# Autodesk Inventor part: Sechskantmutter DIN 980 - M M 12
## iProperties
Shininess: 64.0
Length Units: 11269
Angle Units: 11279
Time Units: 11290
Mass Units: 11283
Length Display Precision: 3
Angle Display Precision: 2
Compacted: True
Part Number: Sechskantmutter DIN 980 - M M 12
Document SubType Name: Standard Catalog Part
Created: 2004-12
Material: Standard
Description: Sechskantmutter, mit Klemmteil, Ganzmetallmutter
Vendor: NORM8
Designer: L.Vaida
Manufacturer: Standard
Standards Organization: Custom
Density: 0.0
Volumn: 0.0
Area: 0.0
PropertySet Name: Model Information
Control State: 0
Master: False
Checked Out: False
CNS_NB: Sechskantmutter DIN 980 - M M 12
CNS_NN: DIN 980
CNS_NT: Sechskantmutter, mit Klemmteil, Ganzmetallmutter
CNS_NBSYN: Sechskantmutter DIN 980 - M $NENN.
CNS_LINA: Sechskantmutter DIN 980 - M M 12
CNS_NENN: M 12
CNS_D: 12.000
CNS_D1: 10.106
CNS_P: 1.750
CNS_M: 12.000
CNS_S: 19.000
CNS_KT: X
PSOL_IDENT_0: {E:\CAD-Programme\cadenas\partsolutions\data\23d-libs\norm\din_en_iso\muttern\muttern_mit_klemmteil\
PSOL_IDENT_1: din_980.prj},166 {M=Nenngewinde},{VTYP=3D},{NB=Sechskantmutter DIN 980 - M M 12},{NN=DIN 980},{DATE=
PSOL_IDENT_2: 29.1.2004},{GEOMDATE=26.11.2003},{VERSION=v1},{LINEID=80},{LINESUBID=-1},{WBVAR=}  {NB=Sechskantmutt
PSOL_IDENT_3: er DIN 980 - M M 12},{LINA=Sechskantmutter DIN 980 - M M 12},{KT=X},{IDNR=},{NENN=M 12},{D=12.000},{
PSOL_IDENT_4: D1=10.106},{P=1.750},{M=12.000},{S=19.000}
Title: Sechskantmutter DIN 980 - M M 12
Author: L.Vaida
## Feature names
1. Drehung1 [Revolution]
2. Extrusion1
